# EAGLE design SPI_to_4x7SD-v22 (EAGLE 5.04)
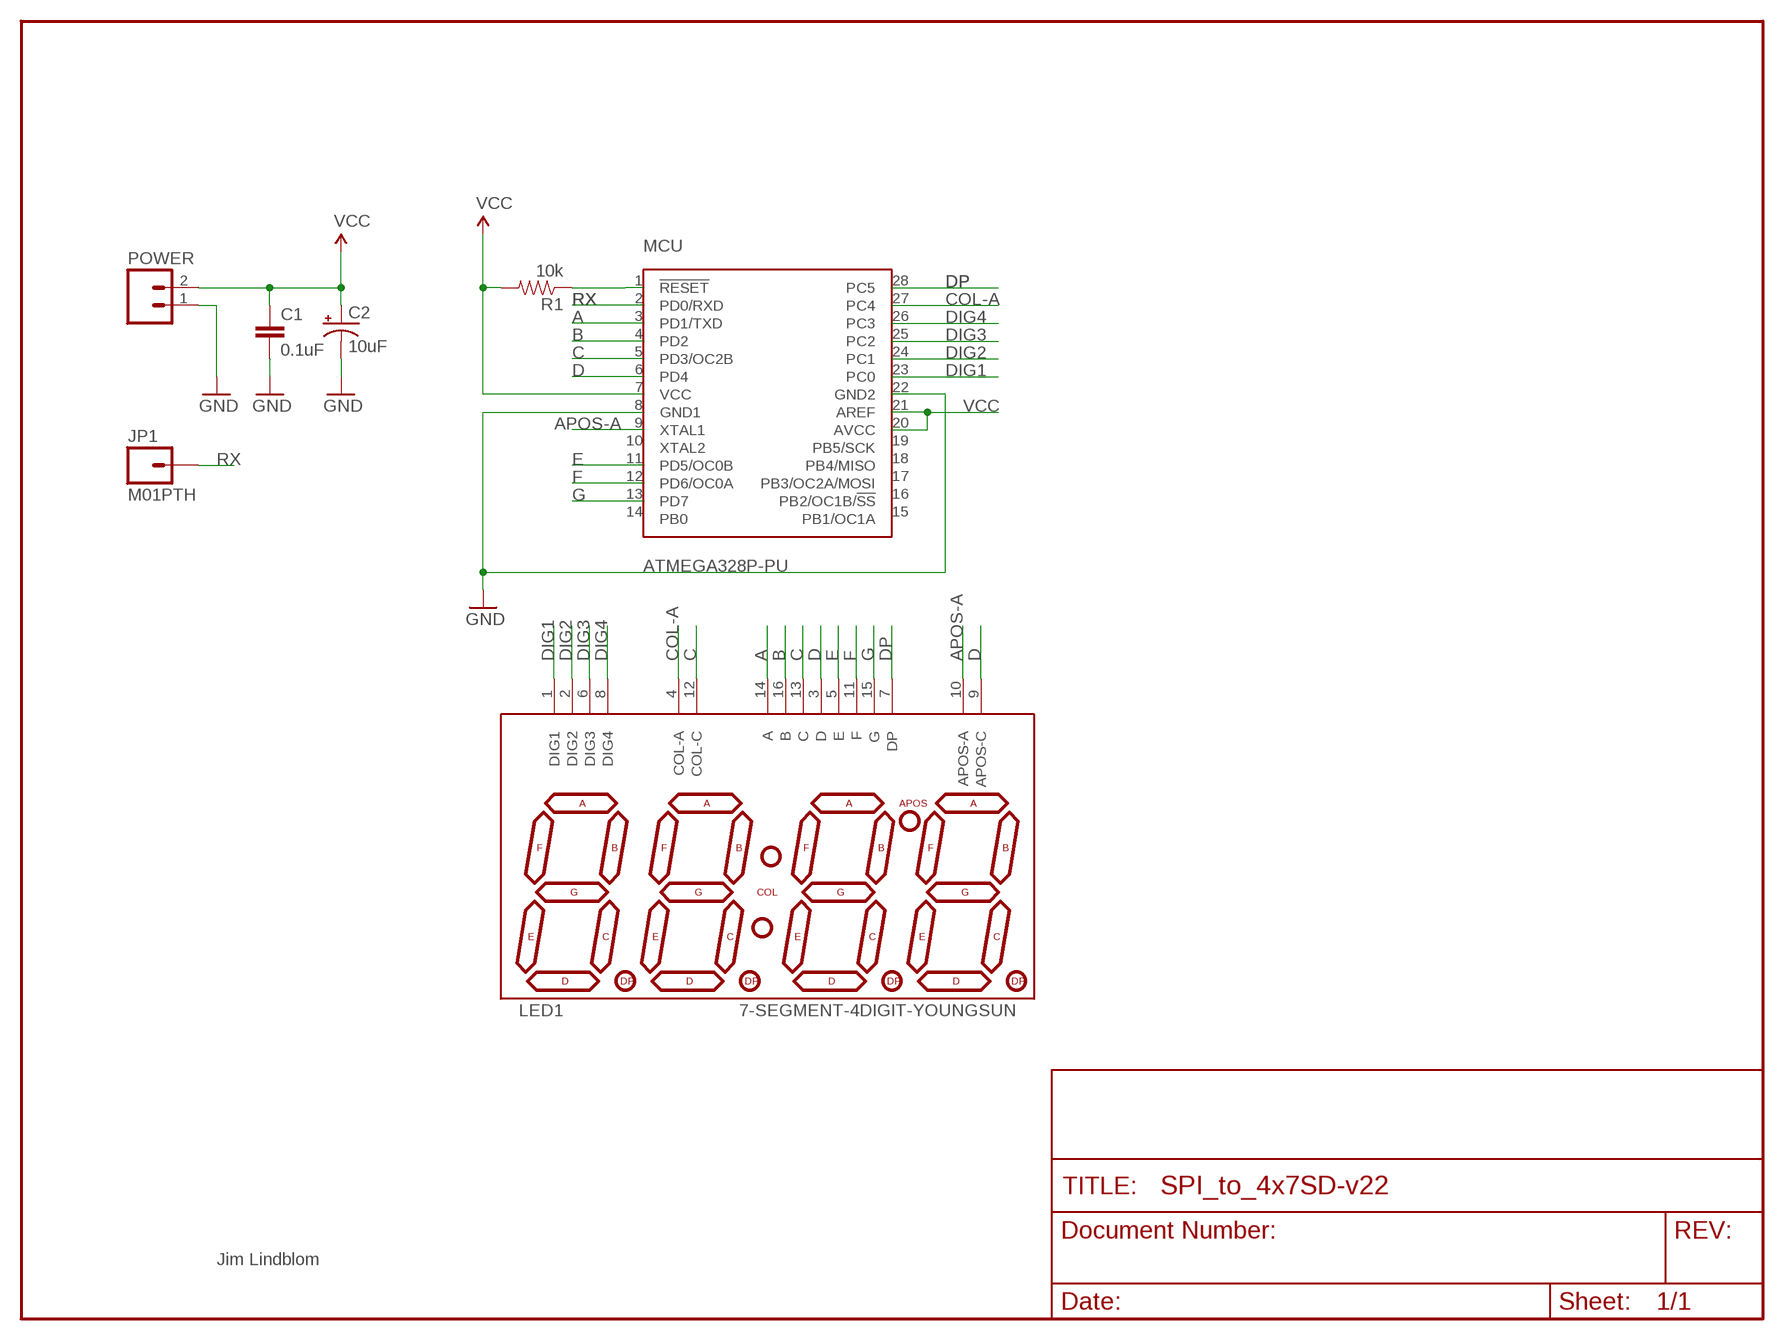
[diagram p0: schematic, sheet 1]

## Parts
C1  0.1uF  CAPPTH  [CAP-PTH-SMALL]
C2  10uF  CAP_POLPTH2  [CPOL-RADIAL-10UF-25V]
JP1  M01PTH  [1X01]
LED1  7-SEGMENT-4DIGIT-YOUNGSUN  [7-SEGMENT-4DIGIT-YOUNGSUN]
MCU  ATMEGA328P-PU  [DIL28-3]
POWER  JP2  M02PTH  [1X02]
R1  10k  RESISTORPTH1  [AXIAL-0.3]

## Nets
A: LED1.14(A) MCU.3(PD1/TXD)
APOS-A: LED1.10(APOS-A) MCU.9(XTAL1)
B: LED1.16(B) MCU.4(PD2)
C: LED1.12(COL-C) LED1.13(C) MCU.5(PD3/OC2B)
COL-A: LED1.4(COL-A) MCU.27(PC4)
D: LED1.3(D) LED1.9(APOS-C) MCU.6(PD4)
DIG1: LED1.1(DIG1) MCU.23(PC0)
DIG2: LED1.2(DIG2) MCU.24(PC1)
DIG3: LED1.6(DIG3) MCU.25(PC2)
DIG4: LED1.8(DIG4) MCU.26(PC3)
DP: LED1.7(DP) MCU.28(PC5)
E: LED1.5(E) MCU.11(PD5/OC0B)
F: LED1.11(F) MCU.12(PD6/OC0A)
G: LED1.15(G) MCU.13(PD7)
GND: C1.2 C2.2(-) MCU.8(GND1) MCU.22(GND2) POWER.1
RST: MCU.1(!RESET) R1.P$1
RX: JP1.1 MCU.2(PD0/RXD)
VCC: C1.1 C2.1(+) MCU.7(VCC) MCU.20(AVCC) MCU.21(AREF) POWER.2 R1.P$2
Unconnected: MCU.10(XTAL2) MCU.14(PB0) MCU.15(PB1/OC1A) MCU.16(PB2/OC1B/!SS) MCU.17(PB3/OC2A/MOSI) MCU.18(PB4/MISO) MCU.19(PB5/SCK)

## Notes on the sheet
- Jim Lindblom

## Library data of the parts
C1 = SparkFun:CAP: Capacitor
C2 = SparkFun:CAP_POL: Capacitor Polarized
JP1 = SparkFun:M01: Header 1
LED1 = SparkFun:7-SEGMENT-4DIGIT-YOUNGSUN: This is a part for the 4-Digit 7-segment LEDs from Young Sun. Different from the Digikey LEDs, all 16 pins are used. The LONGPADS Variant is used for a test jig, but you may like it because there is more pad to solder to. If you are concerned about routing space, the standard works just fine though.
MCU = trl:ATMEGA328P-PU
POWER = SparkFun:M02: Header 2
R1 = SparkFun:RESISTOR: Resistor

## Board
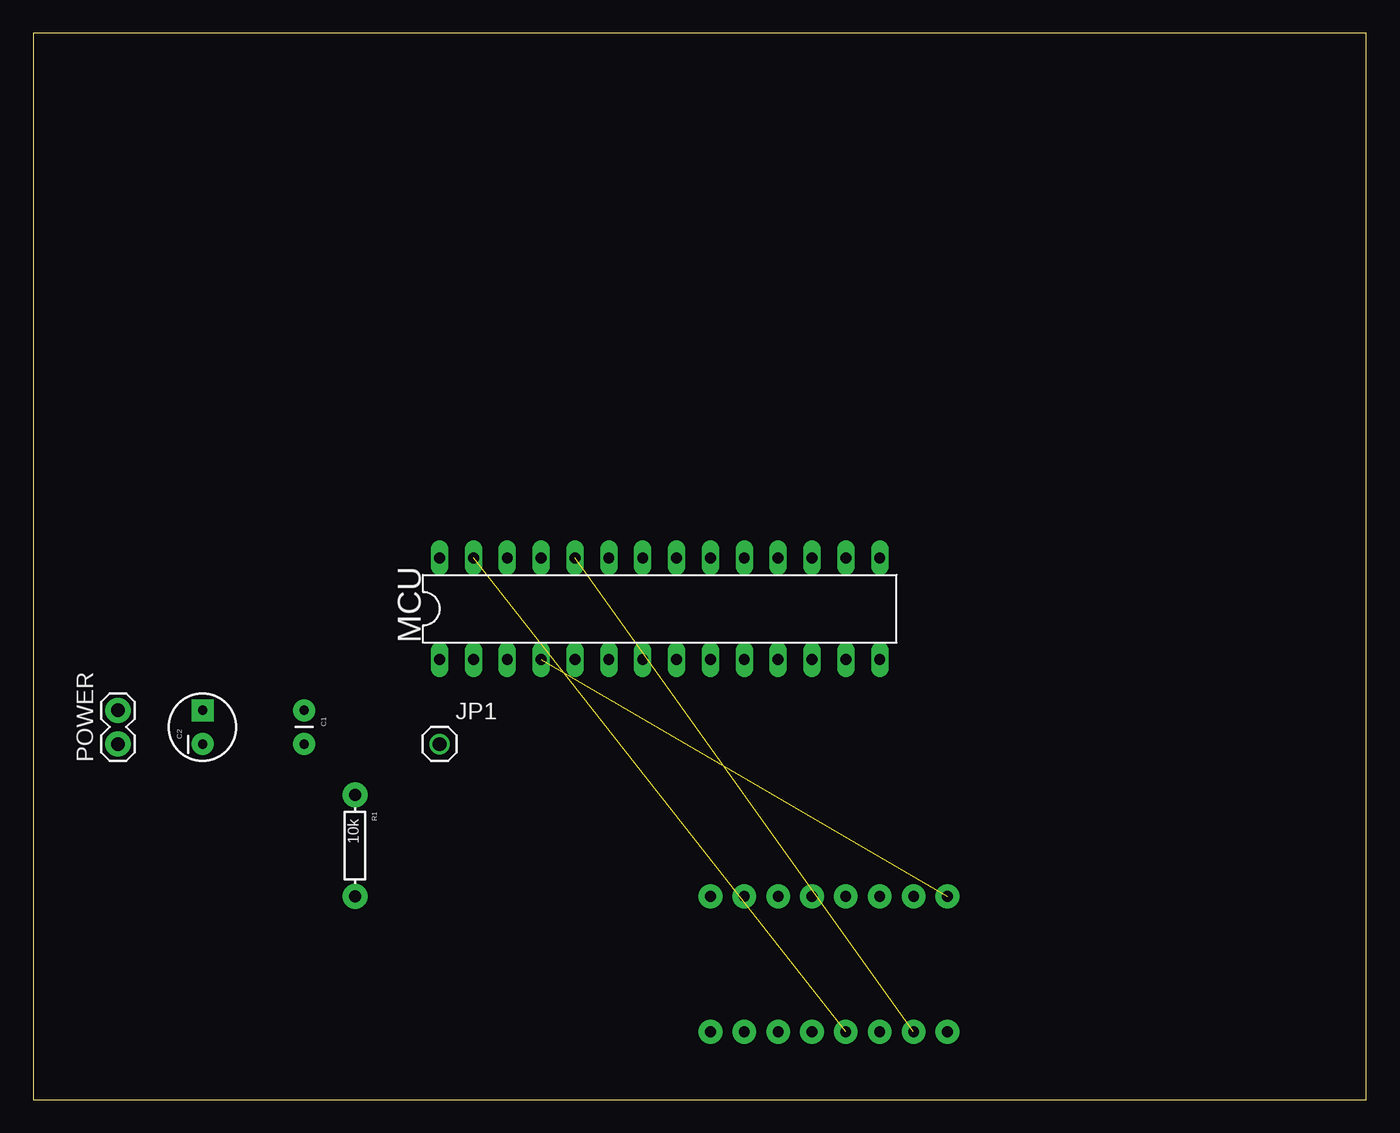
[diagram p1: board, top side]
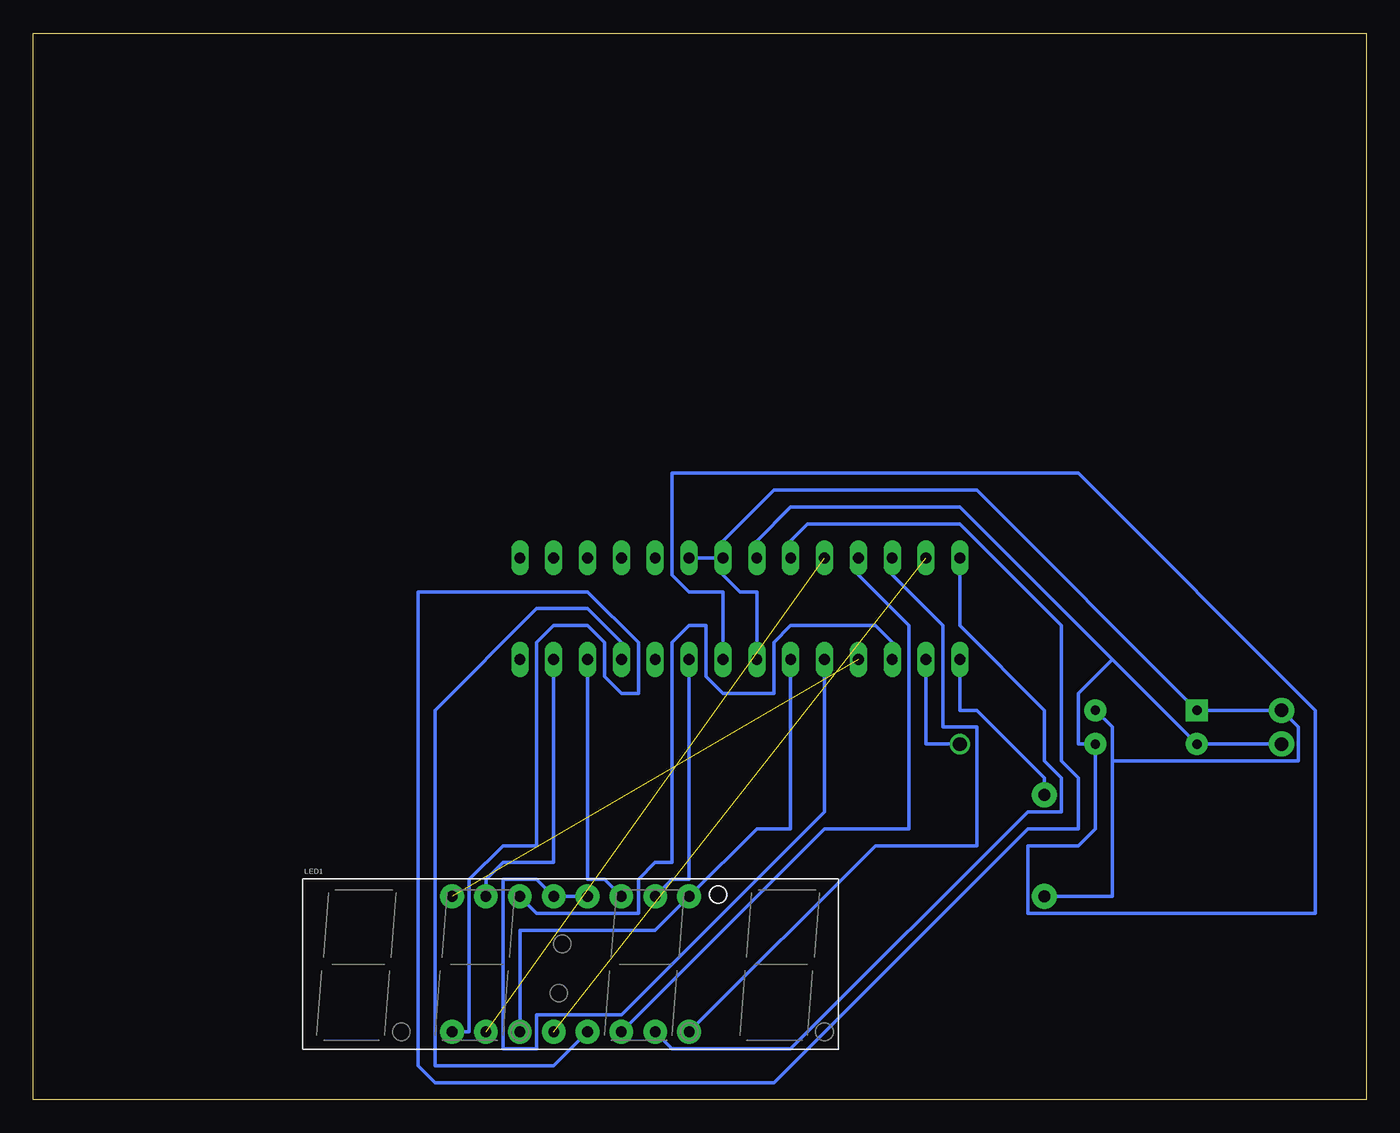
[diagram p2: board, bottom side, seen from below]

Size 100 x 80 mm. Coordinates in mm from the lower left corner, seen from the top.
Outline: 0,0 100,0 100,80 0,80 0,0
Copper layers (1*16): Top 0.035mm / dielectric 1.5mm / Bottom 0.035mm
Design rules "default": minimum track width 10mil, minimum drill 24mil, track to track 8mil, track to pad 8mil, pad to pad 8mil, via to via 8mil, smd to smd 8mil, copper to edge 40mil, drill to drill 8mil, minimum pad ring 10mil, minimum via ring 8mil, stop-mask expansion 4mil, vias tented up to drill 0mil, thermal gap 10mil

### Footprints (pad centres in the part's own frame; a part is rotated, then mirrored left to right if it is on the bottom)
CAP-PTH-SMALL = drill 0.7 pad 1.651 round: 1 0,0; 2 2.54,0
CPOL-RADIAL-10UF-25V = drill 0.7 pad 1.651 square: 1 1.27,0 | drill 0.7 pad 1.651 round: 2 -1.27,0
1X01 = drill 1.016 round: 1 0,0
7-SEGMENT-4DIGIT-YOUNGSUN = drill 0.8 pad 1.778 round: 1 -8.89,-5.08; 2 -6.35,-5.08; 3 -3.81,-5.08; 4 -1.27,-5.08; 5 1.27,-5.08; 6 3.81,-5.08; 7 6.35,-5.08; 8 8.89,-5.08; 9 8.89,5.08; 10 6.35,5.08; 11 3.81,5.08; 12 1.27,5.08; 13 -1.27,5.08; 14 -3.81,5.08; 15 -6.35,5.08; 16 -8.89,5.08
DIL28-3 = drill 0.813 long: 1 -16.51,-3.81; 2 -13.97,-3.81; 3 -11.43,-3.81; 4 -8.89,-3.81; 5 -6.35,-3.81; 6 -3.81,-3.81; 7 -1.27,-3.81; 8 1.27,-3.81; 9 3.81,-3.81; 10 6.35,-3.81; 11 8.89,-3.81; 12 11.43,-3.81; 13 13.97,-3.81; 14 16.51,-3.81; 15 16.51,3.81; 16 13.97,3.81; 17 11.43,3.81; 18 8.89,3.81; 19 6.35,3.81; 20 3.81,3.81; 21 1.27,3.81; 22 -1.27,3.81; 23 -3.81,3.81; 24 -6.35,3.81; 25 -8.89,3.81; 26 -11.43,3.81; 27 -13.97,3.81; 28 -16.51,3.81
1X02 = drill 1.016 pad 1.88 round: 1 0,0; 2 2.54,0
AXIAL-0.3 = drill 0.9 pad 1.88 round: P$1 -3.81,0; P$2 3.81,0

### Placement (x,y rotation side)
C1  20.32,29.21 270 top
C2  12.7,27.94 90 top
JP1  30.48,26.67 0 top
LED1  59.69,10.16 0 bottom
MCU  46.99,36.83 0 top
POWER  6.35,26.67 90 top
R1  24.13,19.05 270 top

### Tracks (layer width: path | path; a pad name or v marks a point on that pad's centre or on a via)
A
  Bottom 0.254: LED1.14 62.23,13.97 54.61,13.97 54.61,16.51 53.34,17.78 52.07,17.78 52.07,34.29 50.8,35.56 49.53,35.56 49.53,31.75 48.26,30.48 44.45,30.48 44.45,34.29 43.18,35.56 36.83,35.56 35.56,34.29 MCU.3
APOS-A
  Bottom 0.254: LED1.10 52.07,16.51 50.8,16.51 50.8,31.75 MCU.9
B  (1 unrouted)
C
  Bottom 0.254: MCU.5 40.64,31.75 40.64,21.59 55.88,6.35 62.23,6.35 62.23,3.81 64.77,3.81 64.77,16.51 62.23,16.51 LED1.13 LED1.12
COL-A  (1 unrouted)
D
  Bottom 0.254: MCU.6 43.18,31.75 43.18,20.32 45.72,20.32 LED1.9 53.34,12.7 63.5,12.7 LED1.3
DIG1
  Bottom 0.254: LED1.1 67.31,5.08 67.31,16.51 64.77,19.05 62.23,19.05 62.23,34.29 60.96,35.56 58.42,35.56 57.15,34.29 57.15,31.75 55.88,30.48 54.61,30.48 54.61,34.29 58.42,38.1 71.12,38.1 71.12,2.54 69.85,1.27 44.45,1.27 25.4,20.32 21.59,20.32 21.59,24.13 22.86,25.4 22.86,35.56 30.48,43.18 41.91,43.18 43.18,41.91 MCU.23
DIG2  (1 unrouted)
DIG3
  Bottom 0.254: LED1.6 40.64,20.32 34.29,20.32 34.29,35.56 38.1,39.37 MCU.25
DIG4
  Bottom 0.254: LED1.8 36.83,19.05 29.21,19.05 29.21,27.94 31.75,27.94 31.75,35.56 35.56,39.37 MCU.26
DP
  Bottom 0.254: LED1.7 52.07,3.81 43.18,3.81 25.4,21.59 22.86,21.59 22.86,24.13 24.13,25.4 24.13,29.21 30.48,35.56 30.48,39.37 MCU.28
E
  Bottom 0.254: LED1.5 60.96,2.54 69.85,2.54 69.85,29.21 62.23,36.83 58.42,36.83 55.88,34.29 MCU.11
F
  Bottom 0.254: LED1.11 57.15,16.51 58.42,16.51 58.42,31.75 MCU.12
G
  Bottom 0.254: LED1.15 66.04,16.51 64.77,17.78 60.96,17.78 60.96,31.75 MCU.13
GND
  Bottom 0.254: 19.05,33.02 C2.2 POWER.1 | 19.05,33.02 30.48,44.45 43.18,44.45 45.72,41.91 MCU.22 | MCU.8 48.26,34.29 48.26,38.1 50.8,38.1 52.07,39.37 52.07,46.99 21.59,46.99 3.81,29.21 3.81,13.97 25.4,13.97 25.4,19.05 21.59,19.05 20.32,20.32 C1.2 21.59,26.67 21.59,30.48 19.05,33.02
RST
  Bottom 0.254: R1.P$1 24.13,24.13 29.21,29.21 30.48,29.21 30.48,31.75 MCU.1
RX
  Bottom 0.254: JP1.1 33.02,26.67 33.02,31.75 MCU.2
VCC
  Bottom 0.254: MCU.7 45.72,34.29 45.72,38.1 46.99,38.1 48.26,39.37 MCU.21 | MCU.21 MCU.20 | C1.1 19.05,27.94 19.05,25.4 | 19.05,25.4 19.05,15.24 R1.P$2 | 19.05,25.4 5.08,25.4 5.08,27.94 POWER.2 C2.1 29.21,45.72 44.45,45.72 48.26,41.91 MCU.21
